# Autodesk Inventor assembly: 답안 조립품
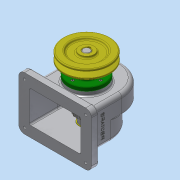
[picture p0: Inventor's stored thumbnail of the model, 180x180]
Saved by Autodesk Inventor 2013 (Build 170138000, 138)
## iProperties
Created: 2017-11
Part Number: 답안 조립품
Document SubType Name: Assembly
Designer: dgall
Author: dgall
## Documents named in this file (14)
- C:\Users\dgall\Desktop\471107V1033\답안 조립품.iam
- C:\Users\dgall\Desktop\471107V1033\본체.ipt
- C:\Users\dgall\Desktop\471107V1033\앞커버.ipt
- C:\Users\dgall\Desktop\471107V1033\뒤커버.ipt
- C:\Users\dgall\Desktop\471107V1033\볼트 M3 x 8.ipt
- C:\Users\dgall\Desktop\471107V1033\축.ipt
- C:\Users\dgall\Desktop\471107V1033\키 - 5 x 5 x 18.ipt
- C:\Users\dgall\Desktop\471107V1033\키 - 6 x 6 x 22.ipt
- C:\Users\dgall\Desktop\471107V1033\스퍼기어.ipt
- C:\Users\dgall\Desktop\471107V1033\베어링 6002.ipt
- C:\Users\dgall\Desktop\471107V1033\V-벨트풀리.ipt
- C:\Users\dgall\Desktop\471107V1033\멈춤나사 - M4 x 10.ipt
- 멈춤나사 - M4 x 10.ipt
- C:\Users\dgall\Desktop\471107V1033\오일 실 15 30 7.ipt
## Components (1 placed, 1 different names)
1. V-벨트풀리:1
